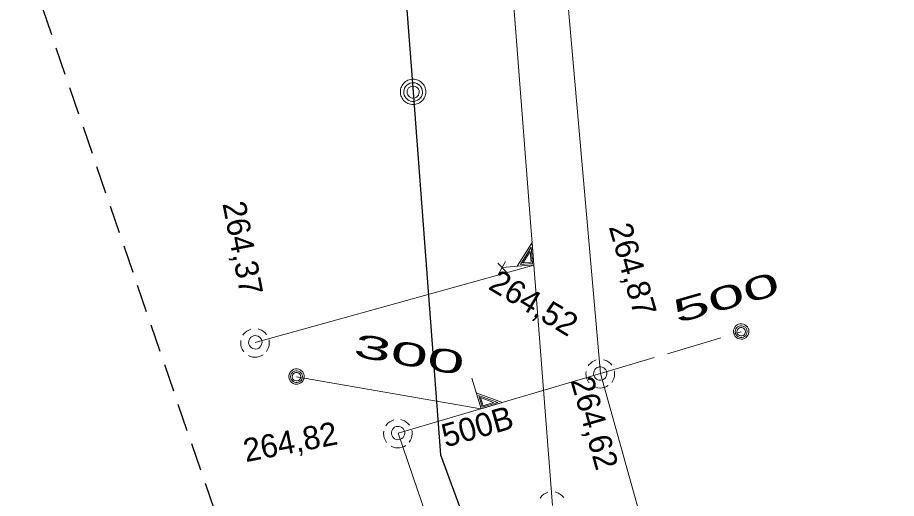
# Model space of a CAD drawing. Extents: x -732074 to -731966, y -1048695 to -1047982.
# Drawn here: x -732074 to -732043.73, y -1048432.1 to -1048415.55 of the extents above; entities that cross this region are included whole.
import ezdxf

# ---------------------------------------------------------------- set-up
doc = ezdxf.new("R2010")
doc.units = 0
doc.header["$LTSCALE"] = 0.32
doc.linetypes.add('LONG_DASHED', pattern=[7.5, 6, -1.5])
doc.linetypes.add('MEDIUM_DASHED', pattern=[4.5, 3, -1.5])
doc.layers.add('1', color=7, linetype='Continuous')
for name, color, linetype, lineweight in [('18', 7, 'Continuous', 13), ('20', 7, 'Continuous', 13), ('49', 7, 'Continuous', 13), ('63', 7, 'MEDIUM_DASHED', 25), ('8', 7, 'Continuous', 13)]:
    doc.layers.add(name, color=color, linetype=linetype, lineweight=lineweight)

msp = doc.modelspace()

# ---------------------------------------------------------------- linework, layer by layer
at = {"layer": '18'}
for p, q in [((-732057.453, -1048423.999), (-732057.159, -1048424.313)), ((-732057.414, -1048424.336), (-732057.199, -1048423.948))]:
    msp.add_line(p, q, dxfattribs=at)
for points in [[(-732057.312, -1048424.15), (-732056.219, -1048424.066), (-732056.279, -1048423.297), (-732056.796, -1048424.11)], [(-732056.682, -1048424.05), (-732056.267, -1048424.018), (-732056.311, -1048423.455), (-732056.683, -1048424.05)], [(-732056.602, -1048423.997), (-732056.312, -1048423.975), (-732056.34, -1048423.605), (-732056.602, -1048423.999)], [(-732065.962, -1048426.277), (-732066.033, -1048426.305), (-732066.1, -1048426.344), (-732066.16, -1048426.392), (-732066.211, -1048426.449), (-732066.235, -1048426.483)], [(-732065.421, -1048426.46), (-732065.471, -1048426.402), (-732065.529, -1048426.352), (-732065.594, -1048426.311), (-732065.665, -1048426.282), (-732065.714, -1048426.268)], [(-732066.307, -1048426.669), (-732066.313, -1048426.746), (-732066.308, -1048426.823), (-732066.291, -1048426.898), (-732066.262, -1048426.969), (-732066.222, -1048427.035), (-732066.206, -1048427.057)], [(-732065.426, -1048427.046), (-732065.385, -1048426.981), (-732065.354, -1048426.911), (-732065.335, -1048426.836), (-732065.327, -1048426.76), (-732065.332, -1048426.683), (-732065.338, -1048426.648)], [(-732066.049, -1048427.186), (-732065.979, -1048427.217), (-732065.904, -1048427.236), (-732065.828, -1048427.243), (-732065.751, -1048427.238), (-732065.676, -1048427.221), (-732065.604, -1048427.193), (-732065.544, -1048427.158)], [(-732054.073, -1048427.337), (-732054.144, -1048427.365), (-732054.211, -1048427.404), (-732054.271, -1048427.452), (-732054.322, -1048427.509), (-732054.346, -1048427.543)], [(-732053.532, -1048427.52), (-732053.582, -1048427.462), (-732053.64, -1048427.412), (-732053.705, -1048427.371), (-732053.776, -1048427.342), (-732053.825, -1048427.328)], [(-732054.418, -1048427.729), (-732054.424, -1048427.806), (-732054.419, -1048427.883), (-732054.402, -1048427.958), (-732054.373, -1048428.029), (-732054.333, -1048428.095), (-732054.317, -1048428.117)], [(-732053.537, -1048428.106), (-732053.496, -1048428.041), (-732053.465, -1048427.971), (-732053.446, -1048427.896), (-732053.438, -1048427.82), (-732053.443, -1048427.743), (-732053.449, -1048427.708)], [(-732058.348, -1048427.968), (-732058.037, -1048429.019), (-732057.298, -1048428.8), (-732058.201, -1048428.464)], [(-732054.16, -1048428.246), (-732054.09, -1048428.277), (-732054.015, -1048428.296), (-732053.939, -1048428.303), (-732053.862, -1048428.298), (-732053.787, -1048428.281), (-732053.715, -1048428.253), (-732053.655, -1048428.218)], [(-732058.118, -1048428.563), (-732058.001, -1048428.962), (-732057.459, -1048428.802), (-732058.119, -1048428.562)], [(-732058.05, -1048428.63), (-732057.967, -1048428.909), (-732057.611, -1048428.804), (-732058.051, -1048428.631)], [(-732061.043, -1048429.397), (-732061.114, -1048429.425), (-732061.181, -1048429.464), (-732061.241, -1048429.512), (-732061.292, -1048429.569), (-732061.316, -1048429.603)], [(-732060.502, -1048429.58), (-732060.552, -1048429.522), (-732060.61, -1048429.472), (-732060.675, -1048429.431), (-732060.746, -1048429.402), (-732060.795, -1048429.388)], [(-732061.388, -1048429.789), (-732061.394, -1048429.866), (-732061.389, -1048429.943), (-732061.372, -1048430.018), (-732061.343, -1048430.089), (-732061.303, -1048430.155), (-732061.287, -1048430.177)], [(-732060.507, -1048430.166), (-732060.466, -1048430.101), (-732060.435, -1048430.031), (-732060.416, -1048429.956), (-732060.408, -1048429.88), (-732060.413, -1048429.803), (-732060.419, -1048429.768)], [(-732061.13, -1048430.306), (-732061.06, -1048430.337), (-732060.985, -1048430.356), (-732060.909, -1048430.363), (-732060.832, -1048430.358), (-732060.757, -1048430.341), (-732060.685, -1048430.313), (-732060.625, -1048430.278)], [(-732055.732, -1048431.887), (-732055.803, -1048431.915), (-732055.87, -1048431.954), (-732055.93, -1048432.002), (-732055.981, -1048432.059), (-732056.005, -1048432.093)], [(-732055.191, -1048432.07), (-732055.241, -1048432.012), (-732055.299, -1048431.962), (-732055.364, -1048431.921), (-732055.435, -1048431.892), (-732055.484, -1048431.878)]]:
    msp.add_lwpolyline(points, dxfattribs=at)
for points in [[(-732048.814, -1048426.356), (-732048.82, -1048426.3), (-732048.837, -1048426.247), (-732048.865, -1048426.198), (-732048.904, -1048426.157), (-732048.95, -1048426.125), (-732049.002, -1048426.103), (-732049.057, -1048426.092), (-732049.113, -1048426.094), (-732049.168, -1048426.107), (-732049.218, -1048426.132), (-732049.263, -1048426.167), (-732049.299, -1048426.21), (-732049.324, -1048426.26), (-732049.339, -1048426.315), (-732049.342, -1048426.371), (-732049.333, -1048426.426), (-732049.312, -1048426.479), (-732049.281, -1048426.525), (-732049.24, -1048426.564), (-732049.193, -1048426.594), (-732049.14, -1048426.613), (-732049.084, -1048426.62), (-732049.027, -1048426.616), (-732048.973, -1048426.599), (-732048.924, -1048426.572), (-732048.883, -1048426.534), (-732048.85, -1048426.489), (-732048.826, -1048426.438), (-732048.815, -1048426.383)], [(-732048.873, -1048426.359), (-732048.879, -1048426.31), (-732048.897, -1048426.264), (-732048.924, -1048426.223), (-732048.962, -1048426.19), (-732049.005, -1048426.168), (-732049.054, -1048426.156), (-732049.103, -1048426.156), (-732049.151, -1048426.168), (-732049.195, -1048426.191), (-732049.232, -1048426.224), (-732049.26, -1048426.265), (-732049.277, -1048426.312), (-732049.282, -1048426.361), (-732049.276, -1048426.41), (-732049.258, -1048426.456), (-732049.23, -1048426.496), (-732049.193, -1048426.529), (-732049.149, -1048426.551), (-732049.1, -1048426.563), (-732049.051, -1048426.562), (-732049.003, -1048426.55), (-732048.96, -1048426.526), (-732048.923, -1048426.493), (-732048.895, -1048426.452), (-732048.879, -1048426.405)], [(-732048.932, -1048426.363), (-732048.938, -1048426.321), (-732048.955, -1048426.283), (-732048.983, -1048426.252), (-732049.017, -1048426.229), (-732049.058, -1048426.218), (-732049.1, -1048426.218), (-732049.14, -1048426.23), (-732049.174, -1048426.253), (-732049.201, -1048426.285), (-732049.218, -1048426.323), (-732049.223, -1048426.364), (-732049.218, -1048426.406), (-732049.2, -1048426.443), (-732049.172, -1048426.475), (-732049.136, -1048426.497), (-732049.096, -1048426.508), (-732049.054, -1048426.507), (-732049.014, -1048426.494), (-732048.98, -1048426.471), (-732048.953, -1048426.438), (-732048.937, -1048426.4)], [(-732065.578, -1048426.729), (-732065.584, -1048426.677), (-732065.602, -1048426.627), (-732065.63, -1048426.583), (-732065.668, -1048426.546), (-732065.713, -1048426.519), (-732065.763, -1048426.503), (-732065.815, -1048426.498), (-732065.867, -1048426.505), (-732065.916, -1048426.524), (-732065.96, -1048426.554), (-732065.995, -1048426.593), (-732066.021, -1048426.638), (-732066.036, -1048426.689), (-732066.039, -1048426.741), (-732066.031, -1048426.793), (-732066.01, -1048426.841), (-732065.98, -1048426.884), (-732065.94, -1048426.919), (-732065.894, -1048426.943), (-732065.843, -1048426.957), (-732065.791, -1048426.959), (-732065.739, -1048426.949), (-732065.691, -1048426.927), (-732065.649, -1048426.895), (-732065.616, -1048426.855), (-732065.592, -1048426.808), (-732065.58, -1048426.757)], [(-732064.126, -1048427.907), (-732064.132, -1048427.851), (-732064.149, -1048427.798), (-732064.178, -1048427.749), (-732064.216, -1048427.708), (-732064.262, -1048427.676), (-732064.314, -1048427.654), (-732064.369, -1048427.643), (-732064.425, -1048427.645), (-732064.48, -1048427.658), (-732064.531, -1048427.683), (-732064.575, -1048427.718), (-732064.611, -1048427.761), (-732064.636, -1048427.811), (-732064.651, -1048427.866), (-732064.654, -1048427.922), (-732064.645, -1048427.977), (-732064.624, -1048428.03), (-732064.593, -1048428.076), (-732064.553, -1048428.115), (-732064.505, -1048428.145), (-732064.452, -1048428.164), (-732064.396, -1048428.171), (-732064.34, -1048428.167), (-732064.286, -1048428.15), (-732064.237, -1048428.123), (-732064.195, -1048428.085), (-732064.162, -1048428.04), (-732064.139, -1048427.989), (-732064.127, -1048427.934)], [(-732064.185, -1048427.91), (-732064.191, -1048427.861), (-732064.209, -1048427.815), (-732064.237, -1048427.774), (-732064.274, -1048427.741), (-732064.318, -1048427.719), (-732064.366, -1048427.707), (-732064.415, -1048427.707), (-732064.463, -1048427.719), (-732064.507, -1048427.742), (-732064.544, -1048427.775), (-732064.572, -1048427.816), (-732064.589, -1048427.863), (-732064.595, -1048427.912), (-732064.588, -1048427.961), (-732064.57, -1048428.007), (-732064.542, -1048428.047), (-732064.505, -1048428.08), (-732064.461, -1048428.102), (-732064.412, -1048428.114), (-732064.363, -1048428.113), (-732064.315, -1048428.101), (-732064.272, -1048428.077), (-732064.235, -1048428.044), (-732064.207, -1048428.003), (-732064.191, -1048427.956)], [(-732053.991, -1048427.58), (-732054.04, -1048427.599), (-732054.083, -1048427.63), (-732054.118, -1048427.669), (-732054.144, -1048427.715), (-732054.158, -1048427.766), (-732054.16, -1048427.818), (-732054.151, -1048427.87), (-732054.13, -1048427.918), (-732054.099, -1048427.96), (-732054.058, -1048427.995), (-732054.011, -1048428.018), (-732053.961, -1048428.031), (-732053.907, -1048428.032), (-732053.857, -1048428.021), (-732053.809, -1048427.999), (-732053.768, -1048427.966), (-732053.735, -1048427.926), (-732053.711, -1048427.878), (-732053.701, -1048427.827), (-732053.701, -1048427.774), (-732053.713, -1048427.723), (-732053.736, -1048427.676), (-732053.77, -1048427.636), (-732053.812, -1048427.604), (-732053.86, -1048427.583), (-732053.912, -1048427.572), (-732053.964, -1048427.574)], [(-732064.244, -1048427.914), (-732064.25, -1048427.872), (-732064.267, -1048427.834), (-732064.295, -1048427.803), (-732064.33, -1048427.78), (-732064.37, -1048427.769), (-732064.412, -1048427.769), (-732064.452, -1048427.781), (-732064.487, -1048427.804), (-732064.514, -1048427.836), (-732064.531, -1048427.874), (-732064.536, -1048427.915), (-732064.53, -1048427.957), (-732064.512, -1048427.994), (-732064.484, -1048428.026), (-732064.448, -1048428.048), (-732064.408, -1048428.059), (-732064.366, -1048428.058), (-732064.326, -1048428.045), (-732064.292, -1048428.022), (-732064.265, -1048427.989), (-732064.249, -1048427.951)], [(-732060.671, -1048429.784), (-732060.691, -1048429.736), (-732060.723, -1048429.693), (-732060.762, -1048429.659), (-732060.809, -1048429.634), (-732060.86, -1048429.621), (-732060.912, -1048429.62), (-732060.964, -1048429.63), (-732061.011, -1048429.651), (-732061.053, -1048429.683), (-732061.087, -1048429.724), (-732061.109, -1048429.772), (-732061.122, -1048429.822), (-732061.122, -1048429.875), (-732061.11, -1048429.926), (-732061.087, -1048429.974), (-732061.054, -1048430.014), (-732061.013, -1048430.046), (-732060.964, -1048430.069), (-732060.914, -1048430.079), (-732060.861, -1048430.078), (-732060.81, -1048430.065), (-732060.763, -1048430.041), (-732060.723, -1048430.006), (-732060.692, -1048429.963), (-732060.672, -1048429.916), (-732060.662, -1048429.864), (-732060.665, -1048429.812)]]:
    msp.add_lwpolyline(points, close=True, dxfattribs=at)
at = {"layer": '20'}
for p, q in [((-732053.92, -1048427.8), (-732056.989, -1048392.94)), ((-732053.92, -1048427.8), (-732056.989, -1048392.94)), ((-732060.89, -1048429.86), (-732053.92, -1048427.8)), ((-732060.89, -1048429.86), (-732053.92, -1048427.8)), ((-732047.59, -1048450.57), (-732053.92, -1048427.8)), ((-732047.59, -1048450.57), (-732053.92, -1048427.8)), ((-732051.489, -1048457.41), (-732060.89, -1048429.86)), ((-732051.489, -1048457.41), (-732060.89, -1048429.86))]:
    msp.add_line(p, q, dxfattribs=at)
at = {"layer": '20', "linetype": 'LONG_DASHED'}
msp.add_line((-732053.92, -1048427.8), (-732049.078, -1048426.369), dxfattribs=at)
msp.add_line((-732053.92, -1048427.8), (-732049.078, -1048426.369), dxfattribs=at)
at = {"layer": '20'}
msp.add_lwpolyline([(-732055.579, -1048432.35), (-732056.217, -1048424.068), (-732057.272, -1048410.408), (-732058.87, -1048389.67)], dxfattribs=at)
msp.add_lwpolyline([(-732055.579, -1048432.35), (-732056.217, -1048424.068), (-732057.272, -1048410.408), (-732058.87, -1048389.67)], dxfattribs=at)
at = {"layer": '49'}
for p, q in [((-732065.809, -1048426.74), (-732056.217, -1048424.068)), ((-732065.809, -1048426.74), (-732056.217, -1048424.068)), ((-732064.39, -1048427.92), (-732058.042, -1048429.018)), ((-732064.39, -1048427.92), (-732058.042, -1048429.018))]:
    msp.add_line(p, q, dxfattribs=at)
at = {"layer": '63'}
msp.add_lwpolyline([(-732022.871, -1048561.909), (-732073.995, -1048412.717), (-732073.996, -1048412.715), (-732073.996, -1048412.713), (-732069.268, -1048320.574)], dxfattribs=at)
at = {"layer": '8', "lineweight": 25}
for points in [[(-732062.206, -1048395.174), (-732062.1, -1048395.76), (-732060.37, -1048418.12)], [(-732060.37, -1048418.12), (-732059.43, -1048430.6), (-732057.43, -1048436.03), (-732055.16, -1048442.06), (-732051.16, -1048452.78), (-732050.93, -1048453.401), (-732046.69, -1048464.651), (-732045.92, -1048466.511), (-732044.12, -1048470.56)]]:
    msp.add_lwpolyline(points, dxfattribs=at)
at = {"layer": '8'}
msp.add_lwpolyline([(-732059.94, -1048418.108), (-732059.942, -1048418.063), (-732059.949, -1048418.018), (-732059.961, -1048417.973), (-732059.977, -1048417.931), (-732059.998, -1048417.89), (-732060.023, -1048417.851), (-732060.052, -1048417.816), (-732060.084, -1048417.783), (-732060.12, -1048417.755), (-732060.157, -1048417.73), (-732060.199, -1048417.709), (-732060.242, -1048417.692), (-732060.286, -1048417.68), (-732060.331, -1048417.673), (-732060.377, -1048417.671), (-732060.423, -1048417.673), (-732060.468, -1048417.68), (-732060.512, -1048417.692), (-732060.555, -1048417.709), (-732060.596, -1048417.73), (-732060.634, -1048417.755), (-732060.67, -1048417.783), (-732060.702, -1048417.816), (-732060.731, -1048417.851), (-732060.756, -1048417.89), (-732060.777, -1048417.931), (-732060.793, -1048417.973), (-732060.805, -1048418.018), (-732060.812, -1048418.063), (-732060.815, -1048418.109), (-732060.812, -1048418.154), (-732060.805, -1048418.199), (-732060.793, -1048418.244), (-732060.777, -1048418.286), (-732060.756, -1048418.327), (-732060.731, -1048418.366), (-732060.702, -1048418.401), (-732060.67, -1048418.434), (-732060.634, -1048418.462), (-732060.596, -1048418.487), (-732060.555, -1048418.508), (-732060.512, -1048418.525), (-732060.468, -1048418.536), (-732060.423, -1048418.544), (-732060.377, -1048418.546), (-732060.331, -1048418.544), (-732060.286, -1048418.536), (-732060.242, -1048418.525), (-732060.199, -1048418.508), (-732060.157, -1048418.487), (-732060.12, -1048418.462), (-732060.084, -1048418.434), (-732060.052, -1048418.401), (-732060.023, -1048418.366), (-732059.998, -1048418.327), (-732059.977, -1048418.286), (-732059.961, -1048418.244), (-732059.949, -1048418.199), (-732059.942, -1048418.154), (-732059.94, -1048418.109)], dxfattribs=at)
for points in [[(-732060.053, -1048418.116), (-732060.059, -1048418.055), (-732060.077, -1048417.995), (-732060.106, -1048417.94), (-732060.145, -1048417.892), (-732060.192, -1048417.852), (-732060.246, -1048417.822), (-732060.305, -1048417.802), (-732060.367, -1048417.795), (-732060.429, -1048417.799), (-732060.489, -1048417.815), (-732060.544, -1048417.843), (-732060.594, -1048417.88), (-732060.635, -1048417.927), (-732060.667, -1048417.98), (-732060.687, -1048418.039), (-732060.697, -1048418.1), (-732060.694, -1048418.162), (-732060.679, -1048418.222), (-732060.653, -1048418.279), (-732060.617, -1048418.329), (-732060.571, -1048418.372), (-732060.519, -1048418.404), (-732060.461, -1048418.427), (-732060.4, -1048418.437), (-732060.338, -1048418.436), (-732060.277, -1048418.423), (-732060.22, -1048418.398), (-732060.169, -1048418.363), (-732060.125, -1048418.319), (-732060.091, -1048418.267), (-732060.067, -1048418.21), (-732060.055, -1048418.149)], [(-732060.167, -1048418.116), (-732060.173, -1048418.067), (-732060.19, -1048418.02), (-732060.218, -1048417.979), (-732060.256, -1048417.946), (-732060.3, -1048417.922), (-732060.348, -1048417.91), (-732060.398, -1048417.909), (-732060.446, -1048417.921), (-732060.491, -1048417.943), (-732060.529, -1048417.976), (-732060.558, -1048418.016), (-732060.577, -1048418.063), (-732060.584, -1048418.112), (-732060.579, -1048418.162), (-732060.562, -1048418.209), (-732060.535, -1048418.251), (-732060.498, -1048418.285), (-732060.455, -1048418.309), (-732060.407, -1048418.323), (-732060.357, -1048418.324), (-732060.308, -1048418.314), (-732060.263, -1048418.292), (-732060.224, -1048418.26), (-732060.194, -1048418.221), (-732060.175, -1048418.175), (-732060.167, -1048418.125)]]:
    msp.add_lwpolyline(points, close=True, dxfattribs=at)

# ---------------------------------------------------------------- texts
at = {"layer": '1'}
for s, rotation, p in [('264,37', 281, (-732066.943, -1048421.956)), ('264,87', 286, (-732053.644, -1048422.755)), ('264,52', 329, (-732057.826, -1048424.872)), ('264,62', 286, (-732054.963, -1048428.037)), ('500B', 16, (-732059.256, -1048430.353)), ('264,82', 11, (-732066.139, -1048430.855))]:
    msp.add_text(s, height=0.8, rotation=rotation, dxfattribs=at).set_placement(p)
for s, rotation, width, p in [('500 ', 16, 2.1, (-732051.287, -1048426.083)), ('300 ', 350, 2.15, (-732062.464, -1048427.205))]:
    msp.add_text(s, height=0.8, rotation=rotation, dxfattribs=dict(at, width=width)).set_placement(p)

doc.saveas('drawing.dxf')
